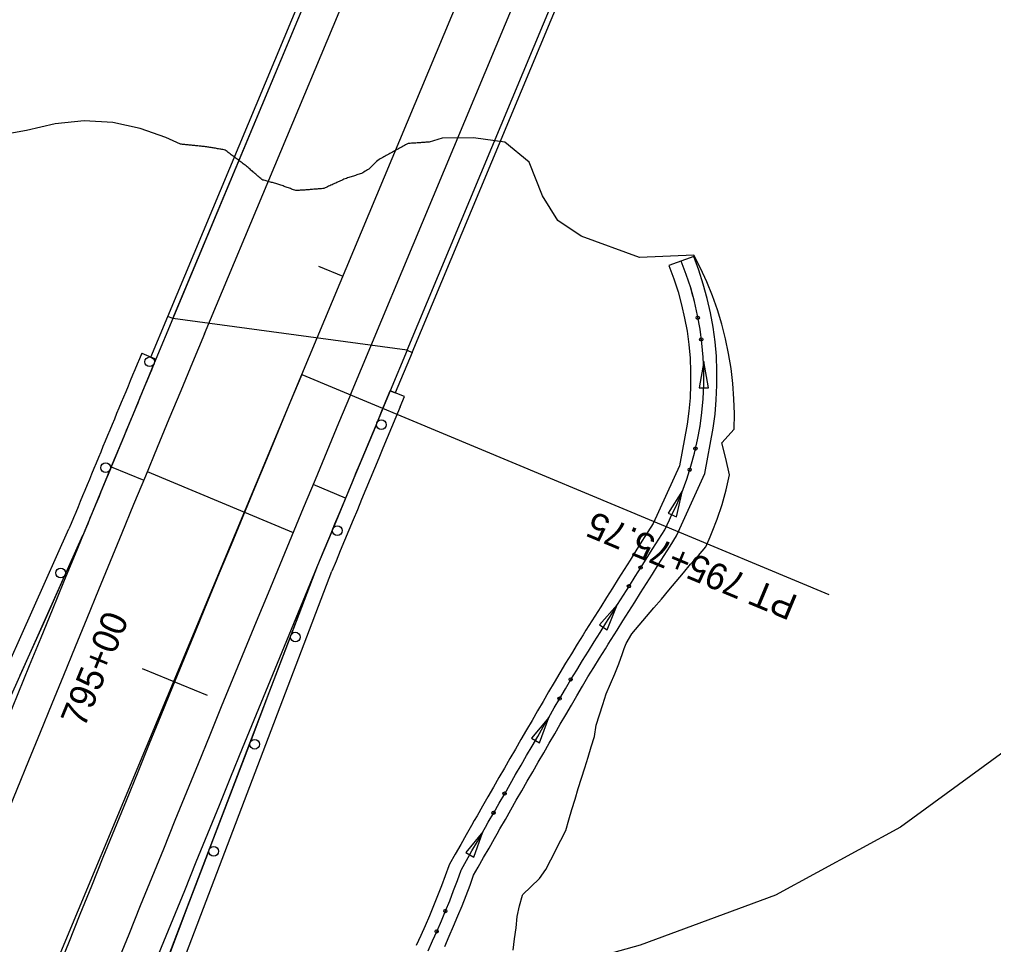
# Model space of a CAD drawing. Extents: x 1237212 to 1293764, y 379349 to 410301.
# Drawn here: x 1283292.5 to 1283514.3, y 403677.5 to 403888.2 of the extents above; entities that cross this region are included whole.
import ezdxf

# ---------------------------------------------------------------- set-up
doc = ezdxf.new("R2010")
doc.units = 0
for name, color, linetype in [('B-Gen-Centerline', 7, 'Continuous'), ('B-Sub-Pier Cap', 7, 'Continuous'), ('B-Tbl-Title Block', 7, 'Continuous'), ('B-Title Block (No Plot)', 7, 'Continuous'), ('R_Axis_Annotation', 7, 'Continuous'), ('R_Bridge', 7, 'Continuous'), ('R_Exist Surface', 7, 'Continuous'), ('R_Grid', 7, 'Continuous'), ('R_Grid Annot', 7, 'Continuous'), ('R_Horz Alg Annot', 7, 'Continuous'), ('R_Prop Surface', 7, 'Continuous'), ('R_Shld', 7, 'Continuous'), ('R_Vert Alg Annot', 7, 'Continuous')]:
    doc.layers.add(name, color=color, linetype=linetype)

msp = doc.modelspace()

# ---------------------------------------------------------------- linework, layer by layer
at = {"layer": 'B-Gen-Centerline'}
for p, q in [((1283322.45, 403811.3), (1283326.31, 403820.53)), ((1283380.81, 403812.87), (1283376.96, 403803.64)), ((1283381.97, 403812.38), (1283378.11, 403803.16)), ((1283380.81, 403812.87), (1283381.97, 403812.38)), ((1283376.96, 403803.64), (1283378.11, 403803.16))]:
    msp.add_line(p, q, dxfattribs=at)
at = {"layer": 'B-Sub-Pier Cap'}
msp.add_line((1283446.03, 403834.22), (1283440.41, 403832.13), dxfattribs=at)
for points in [[(1283448.59, 403784.77), (1283450.45, 403795.08), (1283450.89, 403798.32), (1283451.18, 403801.59), (1283451.33, 403804.88), (1283451.33, 403808.18), (1283451.19, 403811.49), (1283450.89, 403814.8), (1283450.45, 403818.1), (1283449.85, 403821.39), (1283449.11, 403824.66), (1283448.22, 403827.91), (1283447.19, 403831.12), (1283446.03, 403834.22)], [(1283440.41, 403832.13), (1283441.52, 403829.14), (1283442.47, 403826.19), (1283443.29, 403823.21), (1283443.97, 403820.2), (1283444.52, 403817.17), (1283444.93, 403814.13), (1283445.2, 403811.09), (1283445.33, 403808.05), (1283445.33, 403805.02), (1283445.2, 403801.99), (1283444.93, 403798.99), (1283444.52, 403796.01), (1283442.82, 403786.57)], [(1283442.82, 403786.57), (1283436.84, 403773.43), (1283435.6, 403771.48), (1283434.25, 403769.35), (1283432.9, 403767.22), (1283431.56, 403765.09), (1283430.21, 403762.96), (1283428.87, 403760.83), (1283427.53, 403758.7), (1283426.19, 403756.57), (1283424.86, 403754.44), (1283423.52, 403752.3), (1283422.18, 403750.17), (1283421.51, 403749.09), (1283420.85, 403748.03), (1283419.52, 403745.9), (1283418.19, 403743.76), (1283416.84, 403741.59), (1283415.54, 403739.4), (1283414.27, 403737.23), (1283413.01, 403735.07), (1283411.75, 403732.9), (1283410.49, 403730.73), (1283409.23, 403728.57), (1283407.97, 403726.4), (1283406.71, 403724.23), (1283405.46, 403722.06), (1283404.2, 403719.89), (1283402.95, 403717.72), (1283401.7, 403715.54), (1283400.45, 403713.37), (1283399.2, 403711.2), (1283397.96, 403709.02), (1283396.71, 403706.85), (1283396.09, 403705.75), (1283395.47, 403704.67), (1283394.23, 403702.49), (1283392.99, 403700.31), (1283391.75, 403698.14), (1283390.45, 403695.84), (1283390.31, 403695.46), (1283389.49, 403693.16), (1283388.64, 403690.88), (1283387.74, 403688.61), (1283386.82, 403686.34), (1283385.87, 403684.08), (1283384.89, 403681.83), (1283383.89, 403679.58), (1283382.88, 403677.33)], [(1283389.37, 403677.13), (1283390.39, 403679.42), (1283391.38, 403681.72), (1283392.36, 403684.04), (1283393.31, 403686.37), (1283394.24, 403688.72), (1283395.13, 403691.09), (1283395.93, 403693.35), (1283396.97, 403695.17), (1283398.2, 403697.35), (1283399.44, 403699.52), (1283400.68, 403701.7), (1283401.3, 403702.77), (1283401.92, 403703.87), (1283403.16, 403706.04), (1283404.41, 403708.21), (1283405.65, 403710.38), (1283406.9, 403712.55), (1283408.15, 403714.72), (1283409.4, 403716.89), (1283410.65, 403719.06), (1283411.9, 403721.22), (1283413.16, 403723.39), (1283414.42, 403725.55), (1283415.67, 403727.72), (1283416.93, 403729.88), (1283418.19, 403732.04), (1283419.46, 403734.2), (1283420.71, 403736.36), (1283421.97, 403738.48), (1283423.28, 403740.59), (1283424.61, 403742.72), (1283425.94, 403744.86), (1283426.6, 403745.91), (1283427.27, 403746.99), (1283428.61, 403749.12), (1283429.94, 403751.25), (1283431.27, 403753.38), (1283432.61, 403755.51), (1283433.95, 403757.64), (1283435.29, 403759.76), (1283436.63, 403761.89), (1283437.97, 403764.02), (1283439.32, 403766.14), (1283440.67, 403768.27), (1283442.12, 403770.57), (1283448.59, 403784.77)]]:
    msp.add_lwpolyline(points, dxfattribs=at)
at = {"layer": 'B-Tbl-Title Block'}
for p, q in [((1283334.68, 403816.57), (1283508.7, 404233.27)), ((1283367.9, 403802.7), (1283541.92, 404219.39)), ((1283313.45, 403786.35), (1283320.83, 403783.26)), ((1283321.65, 403785.24), (1283354.87, 403771.37)), ((1283366.77, 403779.18), (1283359.38, 403782.26))]:
    msp.add_line(p, q, dxfattribs=at)
for radius in [11483.16, 11447.16]:
    msp.add_arc((1293930.9, 399391.32), radius, 157.333333, 159.572534, dxfattribs=at)
at = {"layer": 'B-Title Block (No Plot)'}
msp.add_line((1283356.82, 403807.32), (1283530.85, 404224.02), dxfattribs=at)
msp.add_line((1283356.82, 403807.32), (1283530.85, 404224.02), dxfattribs=at)
msp.add_arc((1293930.9, 399391.32), 11459.16, 157.333333, 159.572534, dxfattribs=at)
msp.add_arc((1293930.9, 399391.32), 11459.16, 157.333333, 159.572534, dxfattribs=at)
at = {"layer": 'R_Axis_Annotation'}
msp.add_lwpolyline([(1283715.99, 403909.66), (1283691.25, 403887.11), (1283666.96, 403863.7), (1283642.92, 403839.5), (1283618.78, 403815.12), (1283594.64, 403790.92), (1283570.05, 403767.27), (1283545.16, 403744.59), (1283519.52, 403723.51), (1283493.14, 403704.25), (1283464.66, 403688.78), (1283433.84, 403677.4), (1283401.78, 403668.46), (1283369.46, 403660.32), (1283337.74, 403651.63), (1283305.58, 403643.85), (1283273.27, 403636.74), (1283240.75, 403630.06), (1283208.44, 403623.14), (1283176.57, 403615.54), (1283145.16, 403606.85)], dxfattribs=at)
at = {"layer": 'R_Bridge'}
for p, q in [((1283327.46, 403820.05), (1283323.61, 403810.82)), ((1283327.46, 403820.05), (1283326.31, 403820.53)), ((1283323.61, 403810.82), (1283322.45, 403811.3))]:
    msp.add_line(p, q, dxfattribs=at)
at = {"layer": 'R_Exist Surface'}
for points in [[(1283345.25, 403853.88), (1283345.03, 403854.07), (1283344.8, 403854.26), (1283344.58, 403854.45), (1283344.36, 403854.64), (1283344.13, 403854.82), (1283343.9, 403854.99), (1283343.67, 403855.16), (1283343.45, 403855.33), (1283343.22, 403855.5), (1283342.99, 403855.67), (1283342.76, 403855.85), (1283342.54, 403856.02), (1283342.31, 403856.19), (1283342.08, 403856.36), (1283341.85, 403856.53), (1283341.63, 403856.71), (1283341.4, 403856.88), (1283341.17, 403857.05), (1283340.94, 403857.22), (1283340.72, 403857.39), (1283340.49, 403857.56), (1283340.26, 403857.74), (1283340.03, 403857.91), (1283339.8, 403858.08), (1283339.58, 403858.25), (1283339.35, 403858.42), (1283339.11, 403858.5), (1283338.86, 403858.55), (1283338.62, 403858.59), (1283338.37, 403858.63), (1283338.12, 403858.67), (1283337.88, 403858.71), (1283337.63, 403858.75), (1283337.38, 403858.8), (1283337.14, 403858.84), (1283336.89, 403858.88), (1283336.64, 403858.92), (1283336.4, 403858.96), (1283336.15, 403859), (1283335.9, 403859.05), (1283335.66, 403859.09), (1283335.41, 403859.13), (1283335.16, 403859.17), (1283334.91, 403859.2), (1283334.67, 403859.22), (1283334.42, 403859.25), (1283334.17, 403859.28), (1283333.92, 403859.3), (1283333.67, 403859.33), (1283333.42, 403859.36), (1283333.17, 403859.38), (1283332.92, 403859.41), (1283332.68, 403859.43), (1283332.43, 403859.46), (1283332.18, 403859.49), (1283331.93, 403859.51), (1283331.68, 403859.54), (1283331.43, 403859.56), (1283331.18, 403859.59), (1283330.93, 403859.61), (1283330.68, 403859.64), (1283330.43, 403859.66), (1283330.19, 403859.68), (1283329.94, 403859.71), (1283329.69, 403859.73), (1283329.44, 403859.75), (1283329.19, 403859.78), (1283325.83, 403861.32), (1283319.99, 403863.34), (1283313.76, 403864.68), (1283307.27, 403865.06), (1283300.7, 403864.4), (1283294.15, 403862.87)], [(1283294.15, 403862.87), (1283286.96, 403861.62), (1283279.93, 403859.17), (1283273.32, 403855.51), (1283266.36, 403851.47), (1283258.9, 403846.92), (1283254.56, 403839.97), (1283254.17, 403837.89)], [(1283420.43, 403838.87), (1283415.09, 403842.4), (1283411.58, 403848.04), (1283408.57, 403855.66), (1283403.01, 403860.23), (1283395.87, 403861.2), (1283388.8, 403861.16), (1283385.85, 403860.26), (1283385.6, 403860.24), (1283385.34, 403860.22), (1283385.09, 403860.2), (1283384.83, 403860.18), (1283384.58, 403860.16), (1283384.32, 403860.14), (1283384.07, 403860.13), (1283383.81, 403860.11), (1283383.56, 403860.09), (1283383.3, 403860.07), (1283383.05, 403860.05), (1283382.79, 403860.03), (1283382.53, 403860.01), (1283382.28, 403859.99), (1283382.02, 403859.99), (1283381.77, 403859.98), (1283381.52, 403859.96), (1283381.26, 403859.94), (1283381, 403859.92), (1283380.73, 403859.8), (1283380.46, 403859.65), (1283380.19, 403859.51), (1283379.91, 403859.36), (1283379.63, 403859.15), (1283379.35, 403859), (1283379.08, 403858.85), (1283378.81, 403858.7), (1283378.53, 403858.55), (1283378.26, 403858.4), (1283377.98, 403858.25), (1283377.71, 403858.1), (1283377.43, 403857.96), (1283377.16, 403857.81), (1283376.88, 403857.66), (1283376.61, 403857.51), (1283376.34, 403857.36), (1283376.06, 403857.21), (1283375.79, 403857.06), (1283375.51, 403856.91), (1283375.24, 403856.76), (1283374.96, 403856.62), (1283374.69, 403856.47), (1283374.41, 403856.32), (1283374.13, 403856.1), (1283373.84, 403855.82), (1283373.54, 403855.53), (1283373.25, 403855.24), (1283372.95, 403854.96), (1283372.66, 403854.67), (1283372.36, 403854.38), (1283372.07, 403854.1), (1283371.79, 403853.95), (1283371.52, 403853.77), (1283371.24, 403853.6), (1283370.96, 403853.42), (1283370.68, 403853.24), (1283370.41, 403853.11), (1283370.14, 403853.02), (1283369.88, 403852.94), (1283369.61, 403852.85), (1283369.35, 403852.77), (1283369.08, 403852.68), (1283368.82, 403852.6), (1283368.55, 403852.51), (1283368.29, 403852.43), (1283368.02, 403852.34), (1283367.76, 403852.26), (1283367.49, 403852.17), (1283367.23, 403852.09), (1283366.96, 403852), (1283366.69, 403851.9), (1283366.42, 403851.78), (1283366.15, 403851.66), (1283365.88, 403851.53), (1283365.61, 403851.41), (1283365.34, 403851.29), (1283365.07, 403851.17), (1283364.8, 403851.05), (1283364.53, 403850.93), (1283364.26, 403850.8), (1283363.99, 403850.68), (1283363.72, 403850.56), (1283363.45, 403850.44), (1283363.18, 403850.32), (1283362.91, 403850.2), (1283362.64, 403850.07), (1283362.37, 403849.95), (1283362.1, 403849.83), (1283361.83, 403849.71), (1283361.57, 403849.66), (1283361.31, 403849.64), (1283361.05, 403849.62), (1283360.8, 403849.6), (1283360.54, 403849.58), (1283360.29, 403849.56), (1283360.03, 403849.54), (1283359.78, 403849.52), (1283359.52, 403849.5), (1283359.27, 403849.48), (1283359.01, 403849.46), (1283358.75, 403849.44), (1283358.5, 403849.42), (1283358.24, 403849.4), (1283357.99, 403849.38), (1283357.73, 403849.36), (1283357.48, 403849.34), (1283357.22, 403849.32), (1283356.97, 403849.3), (1283356.71, 403849.29), (1283356.46, 403849.28), (1283356.2, 403849.27), (1283355.95, 403849.26), (1283355.69, 403849.25), (1283355.44, 403849.24), (1283355.2, 403849.31), (1283354.96, 403849.39), (1283354.72, 403849.48), (1283354.48, 403849.57), (1283354.24, 403849.65), (1283354, 403849.74), (1283353.76, 403849.83), (1283353.52, 403849.92), (1283353.28, 403850), (1283353.04, 403850.09), (1283352.8, 403850.18), (1283352.56, 403850.26), (1283352.32, 403850.35), (1283352.08, 403850.44), (1283351.84, 403850.53), (1283351.6, 403850.61)], [(1283351.6, 403850.61), (1283351.36, 403850.68), (1283351.11, 403850.75), (1283350.87, 403850.82), (1283350.63, 403850.88), (1283350.38, 403850.95), (1283350.14, 403851.02), (1283349.9, 403851.08), (1283349.66, 403851.15), (1283349.41, 403851.22), (1283349.17, 403851.28), (1283348.93, 403851.35), (1283348.68, 403851.42), (1283348.44, 403851.48), (1283348.2, 403851.55), (1283347.96, 403851.62), (1283347.72, 403851.77), (1283347.5, 403851.96), (1283347.28, 403852.15), (1283347.05, 403852.34), (1283346.83, 403852.53), (1283346.6, 403852.73), (1283346.38, 403852.92), (1283346.15, 403853.11), (1283345.93, 403853.3), (1283345.7, 403853.49), (1283345.48, 403853.68), (1283345.25, 403853.88)], [(1283446.06, 403834.54), (1283433.66, 403834.01), (1283420.43, 403838.87)], [(1283450.23, 403771.49), (1283451.37, 403774.39), (1283452.48, 403777.71), (1283453.42, 403781.08), (1283454.18, 403784.49), (1283453.37, 403788.18), (1283452.47, 403791.75), (1283455.22, 403794.89), (1283455.29, 403798.36), (1283455.2, 403801.82), (1283454.96, 403805.27), (1283454.55, 403808.7), (1283453.99, 403812.1), (1283453.28, 403815.46), (1283452.43, 403818.78), (1283451.43, 403822.05), (1283450.28, 403825.27), (1283449.01, 403828.43), (1283447.59, 403831.52), (1283446.06, 403834.54)], [(1283404.9, 403676.27), (1283405.24, 403678.82), (1283405.6, 403681.35), (1283405.88, 403683.91), (1283406.36, 403686.39), (1283407.08, 403688.78), (1283407.11, 403688.91), (1283408.97, 403690.68), (1283410.95, 403692.55), (1283412.39, 403694.64), (1283413.53, 403696.86), (1283414.09, 403697.95), (1283414.67, 403699.07), (1283415.81, 403701.28), (1283416.89, 403703.52), (1283417.6, 403705.9), (1283418.32, 403708.29), (1283419.05, 403710.67), (1283419.77, 403713.05), (1283420.5, 403715.43), (1283421.24, 403717.81), (1283421.98, 403720.19), (1283422.72, 403722.57), (1283423.46, 403724.94), (1283423.84, 403727.47), (1283424.59, 403729.84), (1283425.34, 403732.22), (1283426.09, 403734.59), (1283427.06, 403736.87), (1283428.05, 403739.15), (1283428.97, 403741.45), (1283429.81, 403743.78), (1283430.23, 403744.94), (1283430.66, 403746.12), (1283431.96, 403748.26), (1283433.61, 403750.26), (1283435.3, 403752.25), (1283436.98, 403754.23), (1283438.67, 403756.21), (1283440.36, 403758.2), (1283442.06, 403760.18), (1283443.68, 403762.18), (1283445.33, 403764.18), (1283447.1, 403766.13), (1283448.81, 403768.1), (1283449.78, 403770.4), (1283450.23, 403771.49)]]:
    msp.add_lwpolyline(points, dxfattribs=at)
at = {"layer": 'R_Grid'}
for points in [[(1283192.36, 403390.81), (1283270.52, 403600.67), (1283356.82, 403807.32)], [(1283356.82, 403807.32), (1283476.78, 403757.22)], [(1283356.82, 403807.32), (1283476.78, 403757.22)]]:
    msp.add_lwpolyline(points, dxfattribs=at)
at = {"layer": 'R_Grid Annot'}
for points in [[(1283360.63, 403832.01), (1283366.17, 403829.7)], [(1283360.63, 403832.01), (1283366.17, 403829.7)], [(1283320.46, 403740.36), (1283335.27, 403734.29)], [(1283320.46, 403740.36), (1283335.27, 403734.29)]]:
    msp.add_lwpolyline(points, dxfattribs=at)
at = {"layer": 'R_Horz Alg Annot'}
for p, q in [((1283448.33, 403810.33), (1283447.27, 403804.33)), ((1283448.33, 403810.33), (1283447.27, 403804.33)), ((1283449.39, 403804.33), (1283448.33, 403810.33)), ((1283449.39, 403804.33), (1283448.33, 403810.33)), ((1283447.27, 403804.33), (1283449.39, 403804.33)), ((1283447.27, 403804.33), (1283449.39, 403804.33)), ((1283443.51, 403780.89), (1283440.19, 403775.79)), ((1283443.51, 403780.89), (1283440.19, 403775.79)), ((1283442.13, 403774.96), (1283443.51, 403780.89)), ((1283442.13, 403774.96), (1283443.51, 403780.89)), ((1283440.19, 403775.79), (1283442.13, 403774.96)), ((1283440.19, 403775.79), (1283442.13, 403774.96)), ((1283428.64, 403754.87), (1283424.56, 403750.34)), ((1283428.64, 403754.87), (1283424.56, 403750.34)), ((1283426.36, 403749.22), (1283428.64, 403754.87)), ((1283426.36, 403749.22), (1283428.64, 403754.87)), ((1283424.56, 403750.34), (1283426.36, 403749.22)), ((1283424.56, 403750.34), (1283426.36, 403749.22)), ((1283413.02, 403729.22), (1283409.09, 403724.56)), ((1283413.02, 403729.22), (1283409.09, 403724.56)), ((1283410.92, 403723.5), (1283413.02, 403729.22)), ((1283410.92, 403723.5), (1283413.02, 403729.22)), ((1283409.09, 403724.56), (1283410.92, 403723.5)), ((1283409.09, 403724.56), (1283410.92, 403723.5)), ((1283398.02, 403703.19), (1283394.13, 403698.5)), ((1283398.02, 403703.19), (1283394.13, 403698.5)), ((1283395.97, 403697.45), (1283398.02, 403703.19)), ((1283395.97, 403697.45), (1283398.02, 403703.19)), ((1283394.13, 403698.5), (1283395.97, 403697.45)), ((1283394.13, 403698.5), (1283395.97, 403697.45))]:
    msp.add_line(p, q, dxfattribs=at)
for points in [[(1283440.75, 403774.79), (1283442.18, 403777.76), (1283443.38, 403780.59), (1283444.46, 403783.48), (1283445.42, 403786.43), (1283446.24, 403789.43), (1283446.93, 403792.47), (1283447.49, 403795.55), (1283447.91, 403798.66), (1283448.19, 403801.79), (1283448.33, 403804.95), (1283448.33, 403808.12), (1283448.19, 403811.29), (1283447.91, 403814.47), (1283447.48, 403817.64), (1283446.91, 403820.8), (1283446.2, 403823.93), (1283445.35, 403827.05), (1283444.35, 403830.13), (1283443.22, 403833.17)], [(1283445.87, 403825.15), (1283445.35, 403827.05), (1283444.35, 403830.13), (1283443.22, 403833.17)], [(1283445.87, 403825.15), (1283445.35, 403827.05), (1283444.35, 403830.13), (1283443.22, 403833.17)], [(1283445.88, 403825.11), (1283445.87, 403825.15)], [(1283445.88, 403825.11), (1283445.87, 403825.15)], [(1283447.46, 403795.38), (1283447.49, 403795.55), (1283447.91, 403798.66), (1283448.19, 403801.79), (1283448.33, 403804.95), (1283448.33, 403808.12), (1283448.24, 403810.33)], [(1283447.46, 403795.38), (1283447.49, 403795.55), (1283447.91, 403798.66), (1283448.19, 403801.79), (1283448.33, 403804.95), (1283448.33, 403808.12), (1283448.24, 403810.33)], [(1283447.45, 403795.34), (1283447.46, 403795.37)], [(1283447.45, 403795.34), (1283447.46, 403795.37)], [(1283436.67, 403767.58), (1283436.77, 403767.75), (1283438.12, 403769.88), (1283439.47, 403772), (1283440.51, 403774.27), (1283440.75, 403774.79), (1283442.18, 403777.76), (1283443.38, 403780.59), (1283443.5, 403780.9)], [(1283436.67, 403767.58), (1283436.77, 403767.75), (1283438.12, 403769.88), (1283439.47, 403772), (1283440.51, 403774.27), (1283440.75, 403774.79), (1283442.18, 403777.76), (1283443.38, 403780.59), (1283443.5, 403780.9)], [(1283385.58, 403676.1), (1283386.6, 403678.36), (1283387.6, 403680.64), (1283388.59, 403682.92), (1283389.55, 403685.21), (1283390.49, 403687.51), (1283391.39, 403689.82), (1283392.27, 403692.14), (1283393.1, 403694.49), (1283393.14, 403694.62), (1283394.31, 403696.67), (1283395.55, 403698.85), (1283396.79, 403701.03), (1283398.03, 403703.2), (1283398.64, 403704.28), (1283399.27, 403705.38), (1283400.51, 403707.55), (1283401.76, 403709.72), (1283403.01, 403711.89), (1283404.25, 403714.07), (1283405.5, 403716.24), (1283406.76, 403718.41), (1283408.01, 403720.58), (1283409.26, 403722.74), (1283410.52, 403724.91), (1283411.78, 403727.08), (1283413.03, 403729.24), (1283414.29, 403731.41), (1283415.56, 403733.57), (1283416.82, 403735.74), (1283418.08, 403737.9), (1283419.4, 403740.04), (1283420.73, 403742.18), (1283422.05, 403744.31), (1283423.38, 403746.45), (1283424.04, 403747.51), (1283424.71, 403748.58), (1283426.04, 403750.72), (1283427.38, 403752.85), (1283428.72, 403754.98), (1283430.05, 403757.11), (1283431.39, 403759.24), (1283432.73, 403761.37), (1283434.08, 403763.5), (1283435.42, 403765.63), (1283436.77, 403767.75), (1283438.12, 403769.88), (1283439.47, 403772), (1283440.51, 403774.27), (1283440.75, 403774.79)], [(1283436.65, 403767.55), (1283436.67, 403767.58)], [(1283436.65, 403767.55), (1283436.67, 403767.58)], [(1283420.7, 403742.14), (1283420.73, 403742.18), (1283422.05, 403744.31), (1283423.38, 403746.45), (1283424.04, 403747.51), (1283424.71, 403748.58), (1283426.04, 403750.72), (1283427.38, 403752.85), (1283428.64, 403754.87)], [(1283420.7, 403742.14), (1283420.73, 403742.18), (1283422.05, 403744.31), (1283423.38, 403746.45), (1283424.04, 403747.51), (1283424.71, 403748.58), (1283426.04, 403750.72), (1283427.38, 403752.85), (1283428.64, 403754.87)], [(1283420.68, 403742.11), (1283420.7, 403742.14)], [(1283420.68, 403742.11), (1283420.7, 403742.14)], [(1283405.5, 403716.23), (1283405.5, 403716.24), (1283406.76, 403718.41), (1283408.01, 403720.58), (1283409.26, 403722.74), (1283410.52, 403724.91), (1283411.78, 403727.08), (1283413.02, 403729.22)], [(1283405.5, 403716.23), (1283405.5, 403716.24), (1283406.76, 403718.41), (1283408.01, 403720.58), (1283409.26, 403722.74), (1283410.52, 403724.91), (1283411.78, 403727.08), (1283413.02, 403729.22)], [(1283405.48, 403716.2), (1283405.5, 403716.23)], [(1283405.48, 403716.2), (1283405.5, 403716.23)], [(1283391.38, 403689.79), (1283391.39, 403689.82), (1283392.27, 403692.14), (1283393.1, 403694.49), (1283393.14, 403694.62), (1283394.31, 403696.67), (1283395.55, 403698.85), (1283396.79, 403701.03), (1283398.02, 403703.19)], [(1283391.38, 403689.79), (1283391.39, 403689.82), (1283392.27, 403692.14), (1283393.1, 403694.49), (1283393.14, 403694.62), (1283394.31, 403696.67), (1283395.55, 403698.85), (1283396.79, 403701.03), (1283398.02, 403703.19)], [(1283391.37, 403689.76), (1283391.38, 403689.79)], [(1283391.37, 403689.76), (1283391.38, 403689.79)]]:
    msp.add_lwpolyline(points, dxfattribs=at)
for centre in [(1283446.97, 403820.25), (1283446.97, 403820.25), (1283447.76, 403815.31), (1283447.76, 403815.31), (1283446.44, 403790.46), (1283446.44, 403790.46), (1283445.12, 403785.63), (1283445.12, 403785.63), (1283433.95, 403763.36), (1283433.95, 403763.36), (1283431.28, 403759.12), (1283431.28, 403759.12), (1283418.03, 403737.89), (1283418.03, 403737.89), (1283415.51, 403733.56), (1283415.51, 403733.56), (1283402.97, 403711.9), (1283402.97, 403711.9), (1283400.47, 403707.55), (1283400.47, 403707.55), (1283389.49, 403685.14), (1283389.49, 403685.14), (1283387.52, 403680.53), (1283387.52, 403680.53)]:
    msp.add_circle(centre, 0.375, dxfattribs=at)
at = {"layer": 'R_Prop Surface'}
for p, q in [((1283375.98, 403801.29), (1283376.96, 403803.64)), ((1283265.94, 403679.14), (1283307, 403770.74)), ((1283298.15, 403600.58), (1283360.39, 403763.76))]:
    msp.add_line(p, q, dxfattribs=at)
for points in [[(1283318.4, 403798.26), (1283323.19, 403809.81)], [(1283376.96, 403803.64), (1283373.9, 403796.32)], [(1283313.62, 403786.71), (1283318.4, 403798.26)], [(1283373.49, 403795.3), (1283368.69, 403783.76)], [(1283307.02, 403770.79), (1283313.2, 403785.69)], [(1283368.69, 403783.76), (1283363.9, 403772.22)], [(1283363.48, 403771.2), (1283360.4, 403763.81)], [(1283303.4, 403762.7), (1283307.02, 403770.79)], [(1283360.4, 403763.81), (1283354.35, 403747.93)], [(1283297.83, 403750.29), (1283302.95, 403761.69)], [(1283292.72, 403738.88), (1283297.83, 403750.29)], [(1283353.95, 403746.9), (1283349.5, 403735.22)], [(1283349.5, 403735.22), (1283345.05, 403723.54)], [(1283344.65, 403722.52), (1283340.2, 403710.84)], [(1283340.2, 403710.84), (1283335.74, 403699.16)], [(1283335.35, 403698.13), (1283330.9, 403686.45)], [(1283330.9, 403686.45), (1283326.44, 403674.77)]]:
    msp.add_lwpolyline(points, dxfattribs=at)
for centre in [(1283322.17, 403810.23), (1283374.93, 403795.9), (1283312.18, 403786.12), (1283364.91, 403771.79), (1283301.94, 403762.14), (1283355.37, 403747.54), (1283346.07, 403723.15), (1283336.77, 403698.77)]:
    msp.add_circle(centre, 1.1, dxfattribs=at)
for radius, start, end in [(11491.16, 157.390099, 157.605879), (11439.16, 157.333333, 157.536379)]:
    msp.add_arc((1293931.6, 399392.99), radius, start, end, dxfattribs=at)
at = {"layer": 'R_Shld'}
for p, q in [((1283327.3, 403819.65), (1283501.32, 404236.35)), ((1283320.38, 403812.17), (1283323.61, 403810.82)), ((1283375.28, 403799.62), (1283376.96, 403803.64)), ((1283380.19, 403802.29), (1283376.96, 403803.64)), ((1283379.21, 403799.94), (1283380.19, 403802.29)), ((1283262.75, 403680.57), (1283303.81, 403772.18)), ((1283301.42, 403599.34), (1283363.66, 403762.52))]:
    msp.add_line(p, q, dxfattribs=at)
for centre, radius, start, end in [((1293931.6, 399392.99), 11494.66, 157.390099, 157.605879), ((1293930.9, 399391.32), 11491.16, 157.381068, 159.572534), ((1293931.6, 399392.99), 11435.66, 157.333333, 157.536379), ((1293930.9, 399391.32), 11439.16, 157.333333, 159.572534)]:
    msp.add_arc(centre, radius, start, end, dxfattribs=at)
at = {"layer": 'R_Vert Alg Annot'}
for p, q in [((1283326.31, 403820.53), (1283390.08, 403973.25)), ((1283327.46, 403820.05), (1283391.24, 403972.77)), ((1283380.81, 403812.87), (1283444.59, 403965.58)), ((1283381.97, 403812.38), (1283445.74, 403965.1)), ((1283327.46, 403820.05), (1283326.31, 403820.53)), ((1283380.81, 403812.87), (1283327.46, 403820.05)), ((1283380.81, 403812.87), (1283381.97, 403812.38))]:
    msp.add_line(p, q, dxfattribs=at)

# ---------------------------------------------------------------- texts
at = {"layer": 'R_Grid'}
msp.add_text('PT 795+75.75', height=6, rotation=157.3333, dxfattribs=at).set_placement((1283470.09, 403756.77))
msp.add_text('PT 795+75.75', height=6, rotation=157.3333, dxfattribs=at).set_placement((1283470.09, 403756.77))
at = {"layer": 'R_Grid Annot'}
msp.add_text('795+00', height=6, rotation=67.7121, dxfattribs=at).set_placement((1283307.29, 403726.69))

doc.saveas('drawing.dxf')
